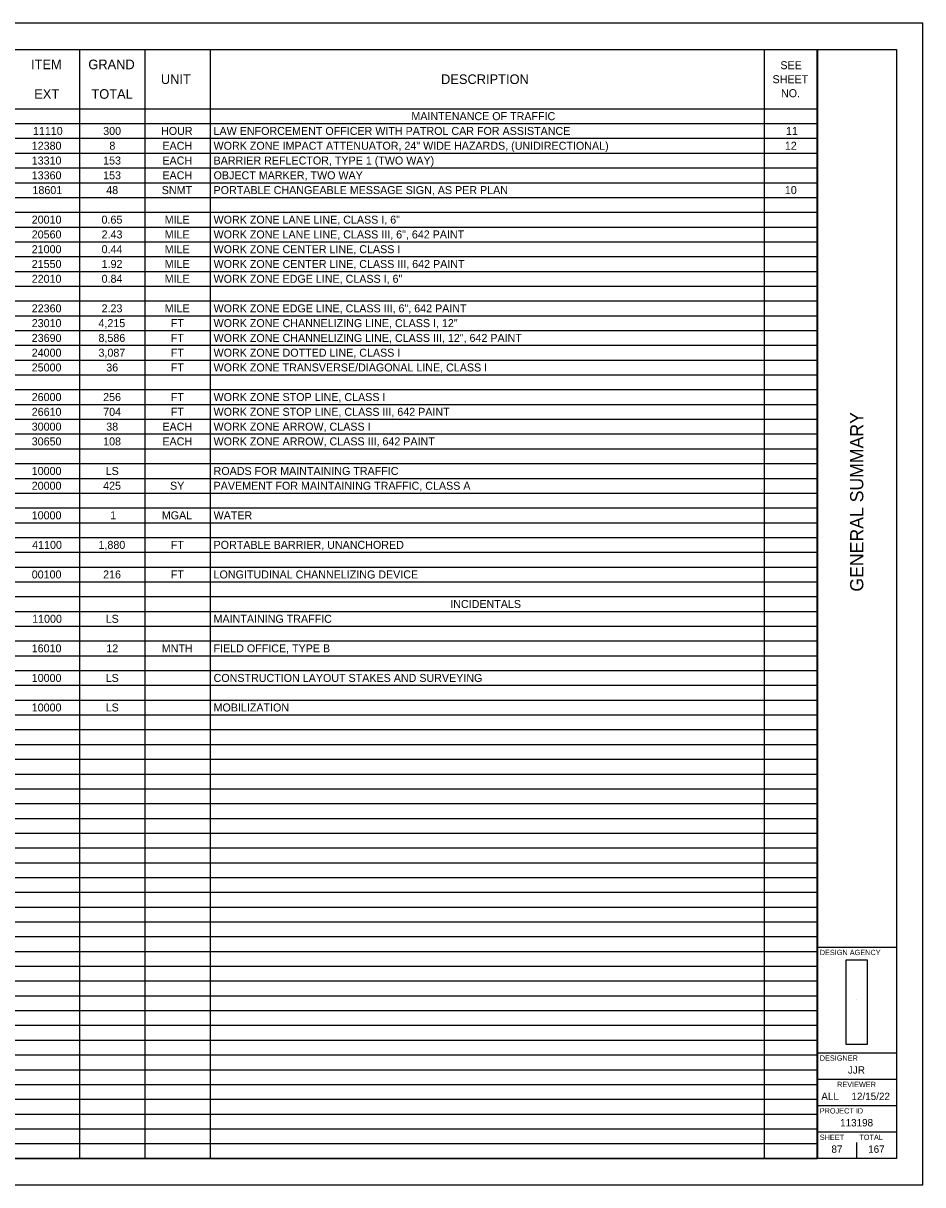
# Model space of a CAD drawing. Extents: x 0 to 34, y 0 to 22.
# Drawn here: x 16.97 to 34, y 0 to 22 of the extents above; entities that cross this region are included whole.
import ezdxf

# ---------------------------------------------------------------- set-up
doc = ezdxf.new("R2010")
doc.units = 0
for name, color, linetype in [('SH_Border', 7, 'Continuous'), ('SH_Cut_Line', 7, 'Continuous'), ('SH_Data', 7, 'Continuous'), ('SH_Text', 7, 'Continuous')]:
    doc.layers.add(name, color=color, linetype=linetype)

msp = doc.modelspace()

# ---------------------------------------------------------------- linework, layer by layer
at = {"layer": 'SH_Border'}
for p, q in [((32, 0.5), (32, 21.5)), ((32, 4.5), (33.5, 4.5)), ((32, 2.5), (33.5, 2.5)), ((32, 2), (33.5, 2)), ((32, 1.5), (33.5, 1.5)), ((32, 1), (33.5, 1))]:
    msp.add_line(p, q, dxfattribs=at)
msp.add_lwpolyline([(1.5, 21.5), (33.5, 21.5), (33.5, 0.5), (1.5, 0.5)], close=True, dxfattribs=at)
at = {"layer": 'SH_Cut_Line'}
msp.add_lwpolyline([(0, 0), (34, 0), (34, 22), (0, 22)], close=True, dxfattribs=at)
at = {"layer": 'SH_Data'}
for p, q in [((32.75, 3.5), (32.75, 3.5)), ((32.375, 0.675), (32.375, 0.675)), ((32.75, 0.5), (32.75, 0.8))]:
    msp.add_line(p, q, dxfattribs=at)
at = {"layer": 'SH_Text'}
for p, q in [((1.5, 21.5), (32.004, 21.5)), ((18.036, 21.5), (18.036, 0.5)), ((19.272, 21.5), (19.272, 0.5)), ((20.507, 21.5), (20.507, 0.5)), ((30.999, 21.5), (30.999, 0.5)), ((32.004, 21.5), (32.004, 0.5)), ((1.5, 20.38), (32.004, 20.38)), ((1.5, 20.1), (32.004, 20.1)), ((1.5, 19.82), (32.004, 19.82)), ((1.5, 19.54), (32.004, 19.54)), ((1.5, 19.26), (32.004, 19.26)), ((1.5, 18.98), (32.004, 18.98)), ((1.5, 18.7), (32.004, 18.7)), ((1.5, 18.42), (32.004, 18.42)), ((1.5, 18.14), (32.004, 18.14)), ((1.5, 17.86), (32.004, 17.86)), ((1.5, 17.58), (32.004, 17.58)), ((1.5, 17.3), (32.004, 17.3)), ((1.5, 17.02), (32.004, 17.02)), ((1.5, 16.74), (32.004, 16.74)), ((1.5, 16.46), (32.004, 16.46)), ((1.5, 16.18), (32.004, 16.18)), ((1.5, 15.9), (32.004, 15.9)), ((1.5, 15.62), (32.004, 15.62)), ((1.5, 15.34), (32.004, 15.34)), ((1.5, 15.06), (32.004, 15.06)), ((1.5, 14.78), (32.004, 14.78)), ((1.5, 14.5), (32.004, 14.5)), ((1.5, 14.22), (32.004, 14.22)), ((1.5, 13.94), (32.004, 13.94)), ((1.5, 13.66), (32.004, 13.66)), ((1.5, 13.38), (32.004, 13.38)), ((1.5, 13.1), (32.004, 13.1)), ((1.5, 12.82), (32.004, 12.82)), ((1.5, 12.54), (32.004, 12.54)), ((1.5, 12.26), (32.004, 12.26)), ((1.5, 11.98), (32.004, 11.98)), ((1.5, 11.7), (32.004, 11.7)), ((1.5, 11.42), (32.004, 11.42)), ((1.5, 11.14), (32.004, 11.14)), ((1.5, 10.86), (32.004, 10.86)), ((1.5, 10.58), (32.004, 10.58)), ((1.5, 10.3), (32.004, 10.3)), ((1.5, 10.02), (32.004, 10.02)), ((1.5, 9.74), (32.004, 9.74)), ((1.5, 9.46), (32.004, 9.46)), ((1.5, 9.18), (32.004, 9.18)), ((1.5, 8.9), (32.004, 8.9)), ((1.5, 8.62), (32.004, 8.62)), ((1.5, 8.34), (32.004, 8.34)), ((1.5, 8.06), (32.004, 8.06)), ((1.5, 7.78), (32.004, 7.78)), ((1.5, 7.5), (32.004, 7.5)), ((1.5, 7.22), (32.004, 7.22)), ((1.5, 6.94), (32.004, 6.94)), ((1.5, 6.66), (32.004, 6.66)), ((1.5, 6.38), (32.004, 6.38)), ((1.5, 6.1), (32.004, 6.1)), ((1.5, 5.82), (32.004, 5.82)), ((1.5, 5.54), (32.004, 5.54)), ((1.5, 5.26), (32.004, 5.26)), ((1.5, 4.98), (32.004, 4.98)), ((1.5, 4.7), (32.004, 4.7)), ((1.5, 4.42), (32.004, 4.42)), ((1.5, 4.14), (32.004, 4.14)), ((1.5, 3.86), (32.004, 3.86)), ((1.5, 3.58), (32.004, 3.58)), ((1.5, 3.3), (32.004, 3.3)), ((1.5, 3.02), (32.004, 3.02)), ((1.5, 2.74), (32.004, 2.74)), ((1.5, 2.46), (32.004, 2.46)), ((1.5, 2.18), (32.004, 2.18)), ((1.5, 1.9), (32.004, 1.9)), ((1.5, 1.62), (32.004, 1.62)), ((1.5, 1.34), (32.004, 1.34)), ((1.5, 1.06), (32.004, 1.06)), ((1.5, 0.78), (32.004, 0.78)), ((1.5, 0.5), (32.004, 0.5))]:
    msp.add_line(p, q, dxfattribs=at)
msp.add_lwpolyline([(32.956, 2.664), (32.956, 4.254), (32.544, 4.254), (32.544, 2.664)], close=True, dxfattribs=at)

# ---------------------------------------------------------------- texts
at = {"layer": 'SH_Data'}
msp.add_text('GENERAL SUMMARY', height=0.25, rotation=90, dxfattribs=at).set_placement((32.875, 11.235))
for s, height, p in [('DESIGN AGENCY', 0.1, (32.05, 4.35)), ('DESIGNER', 0.1, (32.05, 2.35)), ('JJR', 0.14, (32.583, 2.105)), ('REVIEWER', 0.1, (32.378, 1.85)), ('ALL', 0.14, (32.079, 1.605)), ('12/15/22', 0.14, (32.65, 1.605)), ('PROJECT ID', 0.1, (32.05, 1.35)), ('113198', 0.14, (32.435, 1.105)), ('SHEET', 0.1, (32.05, 0.85)), ('TOTAL', 0.1, (32.8, 0.85)), ('87', 0.14, (32.271, 0.605)), ('167', 0.14, (32.966, 0.605))]:
    msp.add_text(s, height=height, dxfattribs=at).set_placement(p)
at = {"layer": 'SH_Text'}
for s, height, p in [('ITEM', 0.1818, (17.117, 21.129)), ('GRAND', 0.1818, (18.202, 21.129)), ('SEE ', 0.1515, (31.304, 21.129)), ('UNIT', 0.1818, (19.575, 20.849)), ('DESCRIPTION', 0.18184, (24.88, 20.849)), ('SHEET ', 0.1515, (31.156, 20.864)), ('EXT', 0.1818, (17.177, 20.569)), ('TOTAL', 0.1818, (18.26, 20.569)), ('NO.', 0.1515, (31.316, 20.599)), ('MAINTENANCE OF TRAFFIC', 0.15153, (24.318, 20.164)), ('11110', 0.1515, (17.153, 19.884)), ('300', 0.1515, (18.483, 19.884)), ('HOUR', 0.1515, (19.579, 19.884)), ('LAW ENFORCEMENT OFFICER WITH PATROL CAR FOR ASSISTANCE', 0.15153, (20.573, 19.884)), ('11', 0.1515, (31.411, 19.884)), ('12380', 0.1515, (17.13, 19.604)), ('8', 0.152, (18.6, 19.604)), ('EACH', 0.1515, (19.604, 19.604)), ('WORK ZONE IMPACT ATTENUATOR, 24" WIDE HAZARDS, (UNIDIRECTIONAL)', 0.15153, (20.573, 19.604)), ('12', 0.1515, (31.389, 19.604)), ('13310', 0.1515, (17.13, 19.324)), ('153', 0.1515, (18.482, 19.324)), ('EACH', 0.1515, (19.604, 19.324)), ('BARRIER REFLECTOR, TYPE 1 (TWO WAY)', 0.15153, (20.573, 19.324)), ('13360', 0.1515, (17.13, 19.044)), ('153', 0.1515, (18.482, 19.044)), ('EACH', 0.1515, (19.604, 19.044)), ('OBJECT MARKER, TWO WAY', 0.15153, (20.573, 19.044)), ('18601', 0.1515, (17.144, 18.764)), ('48', 0.1515, (18.541, 18.764)), ('SNMT', 0.1515, (19.592, 18.764)), ('PORTABLE CHANGEABLE MESSAGE SIGN, AS PER PLAN', 0.15153, (20.573, 18.764)), ('10', 0.1515, (31.389, 18.764)), ('20010', 0.1515, (17.13, 18.204)), ('0.65', 0.1515, (18.452, 18.204)), ('MILE', 0.1515, (19.648, 18.204)), ('WORK ZONE LANE LINE, CLASS I, 6"', 0.15153, (20.573, 18.204)), ('20560', 0.1515, (17.13, 17.924)), ('2.43', 0.1515, (18.453, 17.924)), ('MILE', 0.1515, (19.648, 17.924)), ('WORK ZONE LANE LINE, CLASS III, 6", 642 PAINT', 0.15153, (20.573, 17.924)), ('21000', 0.1515, (17.13, 17.644)), ('0.44', 0.1515, (18.453, 17.644)), ('MILE', 0.1515, (19.648, 17.644)), ('WORK ZONE CENTER LINE, CLASS I', 0.15153, (20.573, 17.644)), ('21550', 0.1515, (17.13, 17.364)), ('1.92', 0.1515, (18.454, 17.364)), ('MILE', 0.1515, (19.648, 17.364)), ('WORK ZONE CENTER LINE, CLASS III, 642 PAINT', 0.15153, (20.573, 17.364)), ('22010', 0.1515, (17.13, 17.084)), ('0.84', 0.1515, (18.453, 17.084)), ('MILE', 0.1515, (19.648, 17.084)), ('WORK ZONE EDGE LINE, CLASS I, 6"', 0.15153, (20.573, 17.084)), ('22360', 0.1515, (17.13, 16.524)), ('2.23', 0.1515, (18.453, 16.524)), ('MILE', 0.1515, (19.648, 16.524)), ('WORK ZONE EDGE LINE, CLASS III, 6", 642 PAINT', 0.15153, (20.573, 16.524)), ('23010', 0.1515, (17.13, 16.244)), ('4,215', 0.1515, (18.394, 16.244)), ('FT', 0.1515, (19.762, 16.244)), ('WORK ZONE CHANNELIZING LINE, CLASS I, 12"', 0.15153, (20.573, 16.244)), ('23690', 0.1515, (17.13, 15.964)), ('8,586', 0.1515, (18.394, 15.964)), ('FT', 0.1515, (19.762, 15.964)), ('WORK ZONE CHANNELIZING LINE, CLASS III, 12", 642 PAINT', 0.15153, (20.573, 15.964)), ('24000', 0.1515, (17.13, 15.684)), ('3,087', 0.1515, (18.394, 15.684)), ('FT', 0.1515, (19.762, 15.684)), ('WORK ZONE DOTTED LINE, CLASS I', 0.15153, (20.573, 15.684)), ('25000', 0.1515, (17.13, 15.404)), ('36', 0.1515, (18.541, 15.404)), ('FT', 0.1515, (19.762, 15.404)), ('WORK ZONE TRANSVERSE/DIAGONAL LINE, CLASS I', 0.15153, (20.573, 15.404)), ('26000', 0.1515, (17.13, 14.844)), ('256', 0.1515, (18.482, 14.844)), ('FT', 0.1515, (19.762, 14.844)), ('WORK ZONE STOP LINE, CLASS I', 0.15153, (20.573, 14.844)), ('26610', 0.1515, (17.13, 14.564)), ('704', 0.1515, (18.483, 14.564)), ('FT', 0.1515, (19.762, 14.564)), ('WORK ZONE STOP LINE, CLASS III, 642 PAINT', 0.15153, (20.573, 14.564)), ('30000', 0.1515, (17.13, 14.284)), ('38', 0.1515, (18.541, 14.284)), ('EACH', 0.1515, (19.604, 14.284)), ('WORK ZONE ARROW, CLASS I', 0.15153, (20.573, 14.284)), ('30650', 0.1515, (17.13, 14.004)), ('108', 0.1515, (18.482, 14.004)), ('EACH', 0.1515, (19.604, 14.004)), ('WORK ZONE ARROW, CLASS III, 642 PAINT', 0.15153, (20.573, 14.004)), ('10000', 0.1515, (17.13, 13.444)), ('LS', 0.1515, (18.53, 13.444)), ('ROADS FOR MAINTAINING TRAFFIC', 0.15153, (20.573, 13.444)), ('20000', 0.1515, (17.13, 13.164)), ('425', 0.1515, (18.482, 13.164)), ('SY', 0.1515, (19.749, 13.164)), ('PAVEMENT FOR MAINTAINING TRAFFIC, CLASS A', 0.15153, (20.573, 13.164)), ('10000', 0.1515, (17.13, 12.604)), ('1', 0.152, (18.615, 12.604)), ('MGAL', 0.1515, (19.593, 12.604)), ('WATER', 0.1515, (20.573, 12.604)), ('41100', 0.1515, (17.138, 12.044)), ('1,880', 0.1515, (18.394, 12.044)), ('FT', 0.1515, (19.762, 12.044)), ('PORTABLE BARRIER, UNANCHORED', 0.15153, (20.573, 12.044)), ('00100', 0.1515, (17.13, 11.484)), ('216', 0.1515, (18.482, 11.484)), ('FT', 0.1515, (19.762, 11.484)), ('LONGITUDINAL CHANNELIZING DEVICE', 0.15153, (20.573, 11.484)), ('INCIDENTALS', 0.15153, (25.054, 10.924)), ('11000', 0.1515, (17.138, 10.644)), ('LS', 0.1515, (18.53, 10.644)), ('MAINTAINING TRAFFIC', 0.15153, (20.573, 10.644)), ('16010', 0.1515, (17.13, 10.084)), ('12', 0.1515, (18.542, 10.084)), ('MNTH', 0.1515, (19.592, 10.084)), ('FIELD OFFICE, TYPE B', 0.15153, (20.573, 10.084)), ('10000', 0.1515, (17.13, 9.524)), ('LS', 0.1515, (18.53, 9.524)), ('CONSTRUCTION LAYOUT STAKES AND SURVEYING', 0.15153, (20.573, 9.524)), ('10000', 0.1515, (17.13, 8.964)), ('LS', 0.1515, (18.53, 8.964)), ('MOBILIZATION', 0.15153, (20.573, 8.964))]:
    msp.add_text(s, height=height, dxfattribs=at).set_placement(p)

doc.saveas('drawing.dxf')
